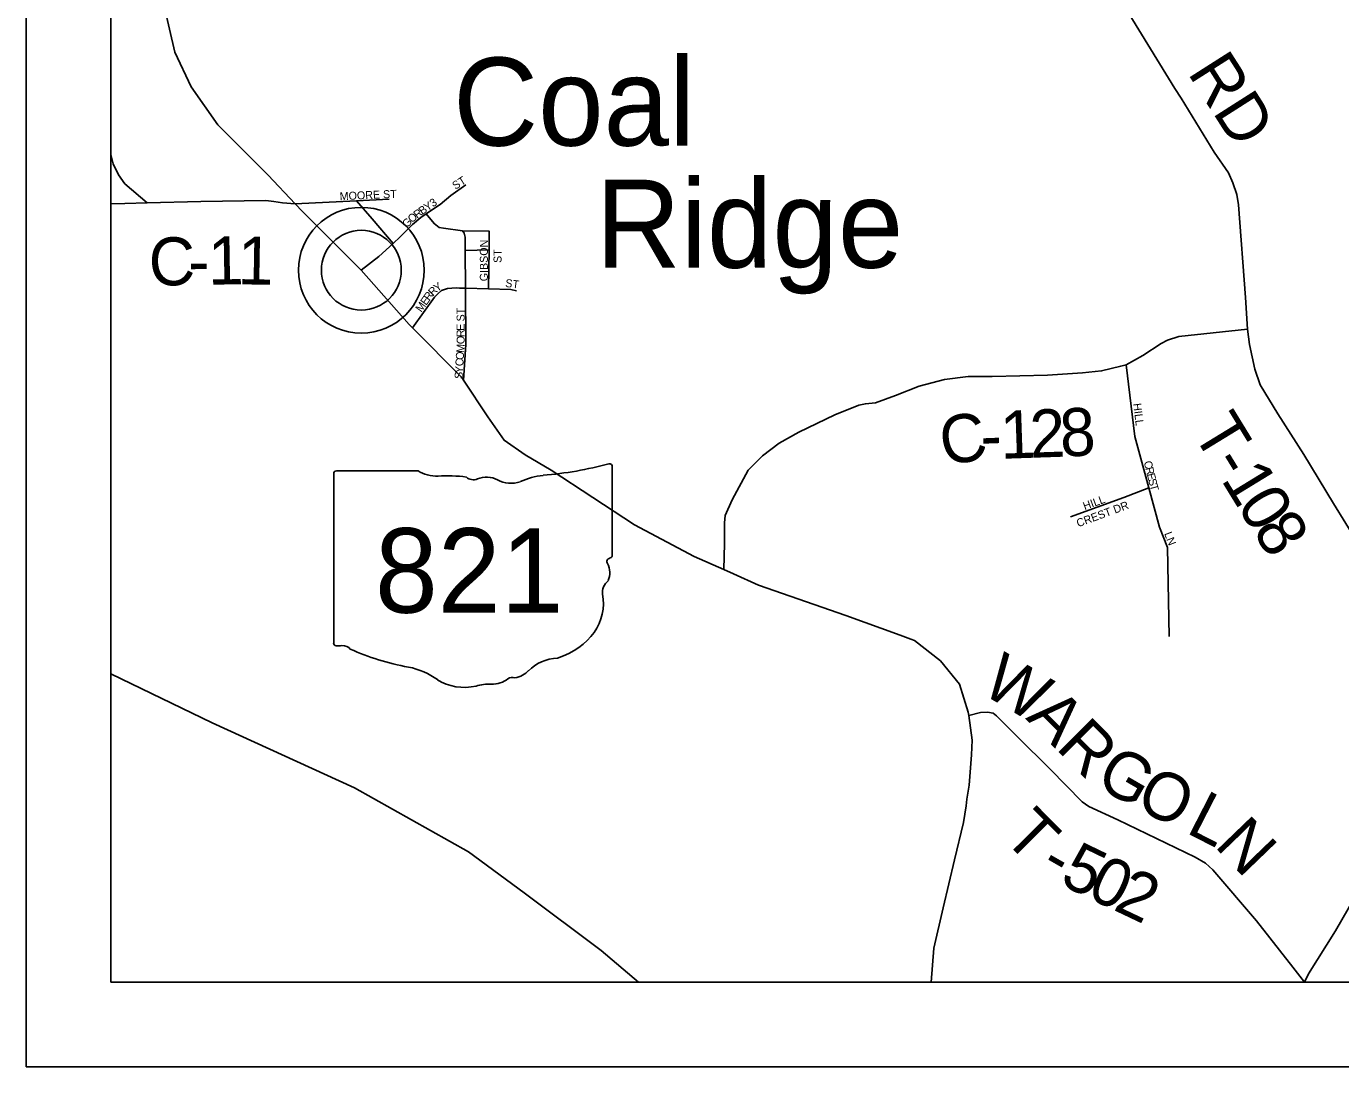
# Model space of a CAD drawing. Extents: x -15 to 405, y -40 to 87.
# Drawn here: x -7.868 to -6.313, y 14.058 to 15.289 of the extents above; entities that cross this region are included whole.
import ezdxf

# ---------------------------------------------------------------- set-up
doc = ezdxf.new("R2010")
doc.units = 0
for name, color, linetype in [('GM_P_State_Location', 7, 'Continuous'), ('GM_X_Major_Lake', 7, 'Continuous'), ('GM_X_Major_River', 7, 'Continuous'), ('GM_X_Minor_Lake', 7, 'Continuous'), ('GM_X_Minor_River', 7, 'Continuous'), ('GM_X_Township', 7, 'Continuous'), ('GM_X_Township_ROW', 7, 'Continuous'), ('GM_X_Township_Subdivision', 7, 'Continuous'), ('GM_X_Township_Subdivision_Text', 7, 'Continuous'), ('GM_X_Township_Text', 7, 'Continuous'), ('GM_X_Unincorporated_Location', 7, 'Continuous')]:
    doc.layers.add(name, color=color, linetype=linetype)

msp = doc.modelspace()

# ---------------------------------------------------------------- linework, layer by layer
at = {"layer": 'GM_P_State_Location'}
msp.add_line((-6.3559, 14.1584), (-6.3559, 14.1583), dxfattribs=at)
for points in [[(-7.7679, 15.1377), (-7.765, 15.1266), (-7.7587, 15.1134), (-7.7513, 15.1029), (-7.7249, 15.0803)], [(-6.4232, 14.9311), (-6.421, 14.9129), (-6.4145, 14.8837), (-6.4084, 14.8651), (-6.3872, 14.8306), (-6.3565, 14.7825), (-6.3216, 14.7245), (-6.2776, 14.6536), (-6.2658, 14.6339), (-6.2605, 14.6195), (-6.2465, 14.5846), (-6.2427, 14.5744), (-6.2393, 14.5683), (-6.2305, 14.5592), (-6.2158, 14.5433), (-6.2113, 14.536), (-6.2093, 14.5308), (-6.2082, 14.5137), (-6.2104, 14.4928), (-6.2111, 14.4904)], [(-6.3559, 14.1584), (-6.3695, 14.1759), (-6.4128, 14.2308), (-6.4643, 14.2914), (-6.473, 14.299), (-6.4852, 14.3062), (-6.5765, 14.3504), (-6.6109, 14.3663), (-6.6189, 14.3716), (-6.6568, 14.4102), (-6.6954, 14.4485), (-6.7201, 14.4735), (-6.7243, 14.4765), (-6.7307, 14.4777), (-6.739, 14.4773), (-6.7531, 14.4739)], [(-6.2967, 14.2581), (-6.3192, 14.2192), (-6.351, 14.1683), (-6.3559, 14.1584)]]:
    msp.add_lwpolyline(points, dxfattribs=at)
at = {"layer": 'GM_X_Major_River'}
for points in [[(-7.4716, 15.0007), (-7.4508, 15.017), (-7.4341, 15.0325), (-7.4256, 15.0403), (-7.4109, 15.0548), (-7.4011, 15.0629), (-7.3947, 15.0675), (-7.3921, 15.0694), (-7.3785, 15.0786), (-7.3657, 15.089), (-7.348, 15.1016)], [(-7.5498, 15.0791), (-7.4774, 15.0827), (-7.4388, 15.0846)], [(-7.4774, 15.0827), (-7.4587, 15.0617), (-7.4341, 15.0325)], [(-7.3508, 14.8707), (-7.3481, 14.9127), (-7.3484, 14.9794), (-7.3486, 15.024), (-7.3487, 15.0398), (-7.3499, 15.0447), (-7.3518, 15.0473), (-7.3742, 15.0506), (-7.3795, 15.0513), (-7.3856, 15.0558), (-7.3947, 15.0675)], [(-7.321, 14.9787), (-7.3205, 15.0247), (-7.3203, 15.0468), (-7.3518, 15.0473)], [(-7.3205, 15.0247), (-7.3486, 15.024)], [(-7.4112, 14.9327), (-7.3849, 14.9689), (-7.3808, 14.9731), (-7.3766, 14.9766), (-7.3695, 14.9789), (-7.3592, 14.9797), (-7.3556, 14.9796)], [(-7.3556, 14.9796), (-7.3554, 14.9796), (-7.3484, 14.9794), (-7.321, 14.9787), (-7.2948, 14.978), (-7.288, 14.9765)], [(-6.516, 14.5672), (-6.5179, 14.6727), (-6.5273, 14.6966), (-6.54, 14.7431), (-6.5565, 14.8038), (-6.5669, 14.8886)], [(-6.6326, 14.7088), (-6.5695, 14.7318), (-6.54, 14.7431)]]:
    msp.add_lwpolyline(points, dxfattribs=at)
at = {"layer": 'GM_X_Township'}
for p, q in [((-7.8679, 21.0583), (-7.8679, 14.0583)), ((-7.7679, 14.1583), (-7.7679, 20.9583)), ((-0.9679, 14.1583), (-7.7679, 14.1583)), ((-7.8679, 14.0583), (-0.8679, 14.0583))]:
    msp.add_line(p, q, dxfattribs=at)
at = {"layer": 'GM_X_Township_Subdivision'}
for p, q in [((-7.5043, 14.7599), (-7.5043, 14.5598)), ((-7.5043, 14.5598), (-7.5043, 14.7599)), ((-7.5043, 14.5598), (-7.5043, 14.7599)), ((-7.501, 14.7633), (-7.4045, 14.7633)), ((-7.1747, 14.7683), (-7.1747, 14.6636)), ((-7.1747, 14.6636), (-7.1747, 14.6636))]:
    msp.add_line(p, q, dxfattribs=at)
for centre, major_axis, start_param, end_param in [((-7.5005, 14.7603), (0.00382, 0), 1.712693, 3.28349), ((-7.3815, 14.7866), (0.037, 0), 4.042523, 4.731795), ((-7.3692, 14.651), (0.133, 0), 1.404758, 1.657858), ((-7.3234, 14.7382), (0.0222, 0), 0.950623, 2.079405), ((-7.2475, 14.7022), (0.0703, 0), 1.699011, 2.107814), ((-7.2921, 15.0362), (0.3495, 0), 4.814394, 5.042369), ((-7.1783, 14.7687), (0.00367, 0), 6.141152, 7.989035), ((-7.339, 14.7613), (0.0107, 0), 3.836095, 5.185415), ((-7.2947, 14.7699), (0.0267, 0), 4.081561, 5.145723), ((-7.1786, 14.6632), (0.00393, 0), 5.05454, 6.418171), ((-7.1755, 14.6559), (0.00568, 0), 1.883978, 3.671073), ((-7.2117, 14.6427), (0.0341, 0), 5.934695, 6.695948), ((-7.1615, 14.6198), (0.0248, 0), 2.387724, 3.262537), ((-7.2725, 14.6065), (0.0874, 0), 5.101752, 6.440018), ((-7.5005, 14.5593), (0.00385, 0), 3.00124, 4.508301), ((-7.4999, 14.5798), (0.0294, 0), 4.665946, 4.897461), ((-7.4939, 14.5482), (0.0106, 0), 0.519207, 1.627899), ((-7.36, 14.728), (0.2524, 0), 4.195997, 4.488961), ((-7.2356, 14.5036), (0.0479, 0), 1.647645, 2.488434), ((-7.4353, 14.4699), (0.079, 0), 0.823519, 1.323587), ((-7.2963, 14.5404), (0.0282, 0), 4.937069, 5.64225), ((-7.3499, 14.5472), (0.0501, 0), 4.026481, 4.996735), ((-7.3209, 14.478), (0.0412, 0), 1.495662, 1.94098), ((-7.3173, 14.5322), (0.0267, 0), 4.691044, 5.507374), ((-7.2931, 14.5129), (0.00752, 0), 1.147584, 2.315152)]:
    msp.add_ellipse(centre, major_axis=major_axis, ratio=0.8, start_param=start_param, end_param=end_param, dxfattribs=at)
at = {"layer": 'GM_X_Township_Subdivision_Text'}
for radius in [0.0744, 0.0472]:
    msp.add_circle((-7.4716, 15.0007), radius, dxfattribs=at)
at = {"layer": 'GM_X_Township_Text'}
for points in [[(-6.5018, 15.2041), (-6.5091, 15.2159), (-6.5701, 15.3149)], [(-6.4232, 14.9311), (-6.4255, 14.9683), (-6.434, 15.0779), (-6.4359, 15.0904), (-6.4408, 15.1041), (-6.4458, 15.1158), (-6.4628, 15.1405), (-6.5018, 15.2041)], [(-7.5498, 15.0791), (-7.5647, 15.0806), (-7.575, 15.0819), (-7.5845, 15.0832), (-7.6613, 15.0819), (-7.7249, 15.0803), (-7.7514, 15.0795), (-7.7679, 15.0793)], [(-7.0428, 14.6464), (-7.0421, 14.6775), (-7.0418, 14.7018), (-7.041, 14.7105), (-7.0327, 14.7291), (-7.0138, 14.764), (-6.9972, 14.7811), (-6.9771, 14.796), (-6.954, 14.8089), (-6.9113, 14.8295), (-6.8829, 14.8409), (-6.8753, 14.8428), (-6.8632, 14.8436), (-6.8397, 14.8523), (-6.8117, 14.8637), (-6.7818, 14.8714), (-6.7538, 14.8748), (-6.7254, 14.8749), (-6.6599, 14.8765), (-6.6186, 14.8792), (-6.5959, 14.8815), (-6.5732, 14.8872), (-6.5669, 14.8886), (-6.547, 14.8998), (-6.5255, 14.9139), (-6.5179, 14.9181), (-6.5046, 14.9223), (-6.4232, 14.9311)]]:
    msp.add_lwpolyline(points, dxfattribs=at)
at = {"layer": 'GM_X_Unincorporated_Location'}
for points in [[(-6.8216, 14.5643), (-6.8342, 14.5689), (-6.8983, 14.5922), (-7.0016, 14.6282), (-7.0314, 14.6414), (-7.0428, 14.6464), (-7.078, 14.662), (-7.1484, 14.6996), (-7.2469, 14.7641), (-7.2777, 14.7822), (-7.3028, 14.7995), (-7.3219, 14.8272), (-7.3508, 14.8707), (-7.3528, 14.8737), (-7.4112, 14.9327), (-7.4149, 14.9365), (-7.4716, 15.0007), (-7.5412, 15.07), (-7.5498, 15.0791), (-7.5818, 15.1131), (-7.6412, 15.1728), (-7.6729, 15.2175), (-7.6924, 15.2588), (-7.7059, 15.3184)], [(-6.7562, 14.367), (-6.7551, 14.3748), (-6.7525, 14.3916), (-6.7496, 14.4273), (-6.749, 14.4448), (-6.7531, 14.4739), (-6.7536, 14.4778), (-6.764, 14.5108), (-6.7865, 14.5384), (-6.817, 14.5626), (-6.8216, 14.5643)], [(-7.7679, 14.5231), (-7.6479, 14.4651), (-7.4796, 14.3881), (-7.3449, 14.3124), (-7.2791, 14.2641), (-7.1878, 14.1958), (-7.1435, 14.1583)], [(-6.7976, 14.1583), (-6.7943, 14.1985), (-6.7831, 14.2464), (-6.7697, 14.3031), (-6.7592, 14.3472), (-6.7562, 14.367)]]:
    msp.add_lwpolyline(points, dxfattribs=at)

# ---------------------------------------------------------------- texts
at = {"layer": 'GM_X_Major_Lake'}
for s, rotation, p in [('ST', 32.7431, (-7.3603, 15.0957)), ('MOORE ST', 2.4588, (-7.497, 15.0835)), ('3', 34.9503, (-7.3867, 15.0749)), ('O', 38.8373, (-7.412, 15.0562)), ('R', 36.6076, (-7.4055, 15.0613)), ('B', 36.0684, (-7.3995, 15.0658)), ('Y', 34.8541, (-7.3935, 15.0702)), ('G', 47.0868, (-7.4174, 15.0503)), ('GIBSON', 90, (-7.3219, 14.9876)), ('ST', 90, (-7.3057, 15.0093)), ('ST', 352.865, (-7.3017, 14.981)), ('R', 54.3494, (-7.3911, 14.9638)), ('R', 45.2232, (-7.3869, 14.9696)), ('Y', 34.2114, (-7.382, 14.9746)), ('M', 54.4708, (-7.4007, 14.9503)), ('E', 54.4734, (-7.3949, 14.9584)), ('ST', 90, (-7.3494, 14.9401)), ('E', 89.9956, (-7.3494, 14.9291)), ('R', 89.994, (-7.3494, 14.9216)), ('M', 86.6464, (-7.35, 14.9027)), ('O', 89.4861, (-7.3494, 14.9132)), ('O', 86.6374, (-7.3505, 14.8944)), ('Y', 86.6374, (-7.3515, 14.8786)), ('C', 86.5979, (-7.351, 14.8869)), ('S', 86.6111, (-7.3519, 14.8719)), ('HILL', 277.1275, (-6.5586, 14.8428)), ('C', 284.1835, (-6.5461, 14.7739)), ('R', 284.195, (-6.5443, 14.7666)), ('E', 284.1887, (-6.5424, 14.7593)), ('S', 284.1887, (-6.5408, 14.7529)), ('T', 285.8553, (-6.5391, 14.7461)), ('CREST DR', 20.3522, (-6.6235, 14.6965)), ('HILL', 20.1333, (-6.6158, 14.7167)), ('LN', 291.2529, (-6.522, 14.6891))]:
    msp.add_text(s, height=0.00947, rotation=rotation, dxfattribs=at).set_placement(p)
at = {"layer": 'GM_X_Minor_Lake'}
for s, height, rotation, p in [('RD', 0.05682, 302.5098, (-6.4949, 15.2345)), ('C', 0.0568, 1.0226, (-7.7226, 14.9823)), ('1', 0.0568, 0.9263, (-7.6526, 14.9835)), ('1', 0.0568, 359.0164, (-7.6182, 14.9841)), ('-', 0.0568, 0.9992, (-7.676, 14.9831)), ('1', 0.0568, 1.9414, (-6.715, 14.7775)), ('2', 0.0568, 1.9462, (-6.6801, 14.7787)), ('8', 0.0568, 2.8385, (-6.6441, 14.7799)), ('C', 0.0568, 9.2948, (-6.7825, 14.7693)), ('-', 0.0568, 2.1939, (-6.7383, 14.7766))]:
    msp.add_text(s, height=height, rotation=rotation, dxfattribs=at).set_placement(p)
at = {"layer": 'GM_X_Minor_River'}
for s, rotation, p in [('T', 301.4525, (-6.4895, 14.8093)), ('-', 301.4551, (-6.4674, 14.7731)), ('1', 301.4984, (-6.4552, 14.7531)), ('0', 301.6451, (-6.4368, 14.7231)), ('8', 302.1899, (-6.4181, 14.6928)), ('W', 329.6052, (-6.7403, 14.5013)), ('A', 315.0386, (-6.6865, 14.4704)), ('R', 315.0304, (-6.6512, 14.435)), ('G', 329.9828, (-6.6053, 14.3922)), ('O', 334.3347, (-6.5579, 14.365)), ('L', 332.8772, (-6.4974, 14.3359)), ('T', 314.8455, (-6.7143, 14.3289)), ('N', 313.9361, (-6.4635, 14.3195)), ('5', 334.2366, (-6.6471, 14.2751)), ('-', 330.1625, (-6.6712, 14.2887)), ('0', 334.4996, (-6.6153, 14.2597)), ('2', 334.5917, (-6.5836, 14.2446))]:
    msp.add_text(s, height=0.0568, rotation=rotation, dxfattribs=at).set_placement(p)
at = {"layer": 'GM_X_Township_ROW'}
for s, p in [('Coal', (-7.363, 15.1481)), ('Ridge', (-7.1943, 15.0036))]:
    msp.add_text(s, height=0.10417, rotation=0, dxfattribs=at).set_placement(p)
at = {"layer": 'GM_X_Township_Subdivision'}
msp.add_text('821', height=0.1, dxfattribs=at).set_placement((-7.4555, 14.5955))

doc.saveas('drawing.dxf')
